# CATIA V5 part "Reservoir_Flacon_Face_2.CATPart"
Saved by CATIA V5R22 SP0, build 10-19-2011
Part number: Reservoir_Flacon_Face
Bounding box of the stored display mesh (mm): x -31 to 31, y 0 to 5, z -112.5 to 112.5
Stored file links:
  U:\S9A\PER\CAO\Assemblage\Reservoir_Flacon\Sous_Ensemble_Flacon\Reservoir_Flacon_Face_2.CATPart
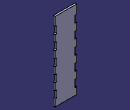
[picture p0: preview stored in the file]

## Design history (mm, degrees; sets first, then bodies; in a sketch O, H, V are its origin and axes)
Body1 (main body)
  Sketch1 on zx-plane, origin (0, 0, 0), H (-1, 0, 0), V (0, 0, 1)
    line L1 (-31, 112.5) -> (31, 112.5)
    line L2 (31, 112.5) -> (31, -112.5)
    line L3 (31, -112.5) -> (-31, -112.5)
    line L4 (-31, -112.5) -> (-31, 112.5)
    length L4 = 225
    length L1 = 62
    horizontal: L1 H, L3 H
    vertical: L2 V, L4 V
    symmetry: L4 L2 V, L1 L3 H
  Pad1: profile Sketch1, direction (0, 1, 0), length 5
  Sketch2 on end face of Pad1, origin (0, 5, 0), H (-1, 0, 0), V (0, 0, 1)
    point P1 (-31, 87.5)
    line L1 (-31, 87.5) -> (-26, 87.5)
    line L2 (-26, 87.5) -> (-26, 67.5)
    line L3 (-26, 67.5) -> (-31, 67.5)
    line L4 (-31, 67.5) -> (-31, 87.5)
    point P2 (-26, 87.5)
    point P3 (-26, 67.5)
    point P4 (-31, 67.5)
    reference projected line E1 (-31, 112.5) -> (-31, -112.5) from edge [face of Pad1 from Sketch1.L4 | end face of Pad1]
    reference projected line E2 (31, 112.5) -> (-31, 112.5) from edge [face of Pad1 from Sketch1.L1 | end face of Pad1]
    point P5 (31, 87.5)
    point P6 (26, 87.5)
    point P7 (26, 67.5)
    point P8 (31, 67.5)
    line L5 (31, 87.5) -> (26, 87.5)
    line L6 (26, 87.5) -> (26, 67.5)
    line L7 (26, 67.5) -> (31, 67.5)
    line L8 (31, 67.5) -> (31, 87.5)
    distance L1 E2 = 25
    length L4 = 20
    length L1 = 5
    horizontal: L1 H, L3 H
    vertical: L2 V, L4 V
    coincidence: L4 E1
    symmetry: P1 P5 V, P2 P6 V, P3 P7 V, P4 P8 V, L1 L5 V, L2 L6 V, L3 L7 V, L4 L8 V
  Pocket1: profile Sketch2, direction (0, -1, 0), through (limit type 6)
  RectPattern1: of Pocket1, direction 1 instances 5, spacing 40, along edge [face of Pad1 from Sketch1.L4 | end face of Pad1]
